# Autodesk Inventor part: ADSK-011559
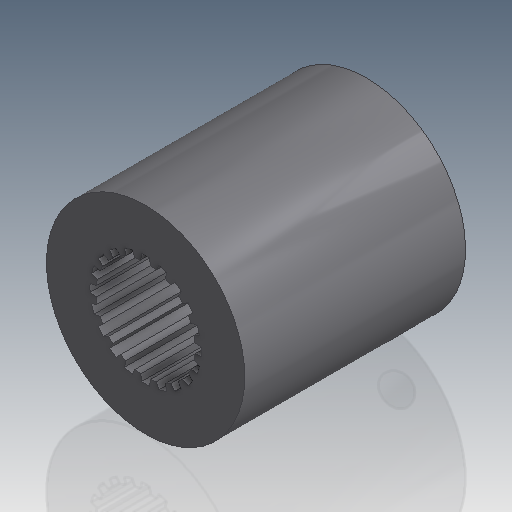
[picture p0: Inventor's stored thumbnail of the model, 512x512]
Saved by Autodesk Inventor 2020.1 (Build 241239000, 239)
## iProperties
Created: 2000-01
Part Number: ADSK-011559
Material: Pearson CRS
Document SubType Name: Modeling
Designer: tgregory
Density: 7.83 g/cm^3
Appearance: Metal-Steel(Polish)
Mass: 895.599 g
Surface Area: 250.505 cm^2
Volume: 114.381 cm^3
Control State: 0
Master: False
Checked Out: False
Shininess: 0.0
Length Units: 11269
Angle Units: 11279
Time Units: 11290
Mass Units: 11283
Length Display Precision: 3
Angle Display Precision: 2
Compacted: True
Dimensions: 57x63,5x57 mm
Mass: 0,896 kg
VLT_Material: Pearson CRS
Density: 0.0
Volumn: 0.0
Area: 0.0
PropertySet Name: Model Information
Author: tgregory
Revision Number: -
Title: ADSK-011559
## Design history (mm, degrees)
node "Solide1"
  node "Extrusion1" dims "d8" = 25, "d9" = 0
  node "Extrusion2" dims "d14" = 63.5, "d15" = 0
  node "Extrusion3" dims "d16" = 50.8, "d17" = 0
  node "Hole1" dims "d22" = 8.376, "d23" = 9.525, "d24" = 6.35, "d25" = 60 deg, "d26" = 27.3, "d27" = 118 deg, "d34" = 20
  node "Hole2" dims "d28" = 8.376, "d29" = 9.525, "d30" = 6.35, "d31" = 60 deg, "d32" = 27.3, "d33" = 118 deg, "d35" = 20
sketch "Sketch1"
  geometry: L1 (0, 16)-(0, 0) reference; L2 (1.4, 14.181)-(1.15, 15.959); L3 (-1.15, 15.959)-(-1.4, 14.181); A1 r 14.25 centre (0, 0) between (1.4, 14.181) and (-1.4, 14.181); A2 r 16 centre (0, 0) between (1.15, 15.959) and (-1.15, 15.959); 1 further point
  constraints: 6 end point, 4 point on circle, 3 coincident, 2 centre point, 1 vertical
  dimensions: "d0" = 28.5 diameter of A1; "d1" = 32 diameter of A2; "d4" = 1.15 distance from line of L2.end L1; "d5" = 1.4 distance from line of L2.start L1; "d6" = 1.15 distance from line of L3.start L1 (= d4); "d7" = 1.4 distance from line of L3.end L1 (= d5)
sketch "Sketch3"
  geometry: L1 (-28.5, 0)-(28.5, 0) reference; L2 (-28.5, 0)-(28.5, 0); L3 (28.5, 0)-(28.5, -25); L4 (28.5, -25)-(-28.5, -25); L5 (-28.5, -25)-(-28.5, 0); 2 further points
  constraints: 8 end point, 2 perpendicular, 1 horizontal, 1 parallel, 1 point on line, 1 other
workplane "Work Plane2"
workplane "Work Plane3"
workplane "Work Plane4"
workaxis "Work Axis2"
workaxis "Work Axis3"
workaxis "Work Axis1"
sketch "Sketch2"
  geometry: L1 (-5.714, -13.054)-(-6.025, -14.822) reference; L2 (-3.838, -15.533)-(-3.051, -13.92) reference; L3 (-1.4, -14.181)-(-1.15, -15.959) reference; L4 (1.15, -15.959)-(1.4, -14.181) reference; L5 (3.051, -13.92)-(3.838, -15.533) reference; L6 (6.025, -14.822)-(5.714, -13.054) reference; L7 (7.203, -12.296)-(8.45, -13.587) reference; L8 (10.311, -12.235)-(9.468, -10.65) reference; L9 (10.65, -9.468)-(12.235, -10.311) reference; L10 (13.587, -8.45)-(12.296, -7.203) reference; L11 (13.054, -5.714)-(14.822, -6.025) reference; L12 (15.533, -3.838)-(13.92, -3.051) reference; L13 (14.181, -1.4)-(15.959, -1.15) reference; L14 (15.959, 1.15)-(14.181, 1.4) reference; L15 (13.92, 3.051)-(15.533, 3.838) reference; L16 (14.822, 6.025)-(13.054, 5.714) reference; L17 (12.296, 7.203)-(13.587, 8.45) reference; L18 (12.235, 10.311)-(10.65, 9.468) reference; L19 (9.468, 10.65)-(10.311, 12.235) reference; L20 (8.45, 13.587)-(7.203, 12.296) reference; L21 (5.714, 13.054)-(6.025, 14.822) reference; L22 (3.838, 15.533)-(3.051, 13.92) reference; L23 (1.4, 14.181)-(1.15, 15.959) reference; L24 (-1.15, 15.959)-(-1.4, 14.181) reference; L25 (-3.051, 13.92)-(-3.838, 15.533) reference; L26 (-6.025, 14.822)-(-5.714, 13.054) reference; L27 (-7.203, 12.296)-(-8.45, 13.587) reference; L28 (-10.311, 12.235)-(-9.468, 10.65) reference; L29 (-10.65, 9.468)-(-12.235, 10.311) reference; L30 (-13.587, 8.45)-(-12.296, 7.203) reference; L31 (-13.054, 5.714)-(-14.822, 6.025) reference; L32 (-15.533, 3.838)-(-13.92, 3.051) reference; L33 (-14.181, 1.4)-(-15.959, 1.15) reference; L34 (-15.959, -1.15)-(-14.181, -1.4) reference; L35 (-13.92, -3.051)-(-15.533, -3.838) reference; L36 (-14.822, -6.025)-(-13.054, -5.714) reference; L37 (-12.296, -7.203)-(-13.587, -8.45) reference; L38 (-12.235, -10.311)-(-10.65, -9.468) reference; L39 (-9.468, -10.65)-(-10.311, -12.235) reference; L40 (-8.45, -13.587)-(-7.203, -12.296) reference; C1 r 28.5 at (0, 0); A1 r 16 centre (0, 0) between (-6.025, -14.822) and (-3.838, -15.533) reference; A2 r 14.25 centre (0, 0) between (-3.051, -13.92) and (-1.4, -14.181) reference; A3 r 16 centre (0, 0) between (-1.15, -15.959) and (1.15, -15.959) reference; A4 r 14.25 centre (0, 0) between (1.4, -14.181) and (3.051, -13.92) reference; A5 r 16 centre (0, 0) between (3.838, -15.533) and (6.025, -14.822) reference; A6 r 14.25 centre (0, 0) between (5.714, -13.054) and (7.203, -12.296) reference; A7 r 16 centre (0, 0) between (8.45, -13.587) and (10.311, -12.235) reference; A8 r 14.25 centre (0, 0) between (9.468, -10.65) and (10.65, -9.468) reference; A9 r 16 centre (0, 0) between (12.235, -10.311) and (13.587, -8.45) reference; A10 r 14.25 centre (0, 0) between (12.296, -7.203) and (13.054, -5.714) reference; A11 r 16 centre (0, 0) between (14.822, -6.025) and (15.533, -3.838) reference; A12 r 14.25 centre (0, 0) between (13.92, -3.051) and (14.181, -1.4) reference; A13 r 16 centre (0, 0) between (15.959, -1.15) and (15.959, 1.15) reference; A14 r 14.25 centre (0, 0) between (14.181, 1.4) and (13.92, 3.051) reference; A15 r 16 centre (0, 0) between (15.533, 3.838) and (14.822, 6.025) reference; A16 r 14.25 centre (0, 0) between (13.054, 5.714) and (12.296, 7.203) reference; A17 r 16 centre (0, 0) between (13.587, 8.45) and (12.235, 10.311) reference; A18 r 14.25 centre (0, 0) between (10.65, 9.468) and (9.468, 10.65) reference; A19 r 16 centre (0, 0) between (10.311, 12.235) and (8.45, 13.587) reference; A20 r 14.25 centre (0, 0) between (7.203, 12.296) and (5.714, 13.054) reference; A21 r 16 centre (0, 0) between (6.025, 14.822) and (3.838, 15.533) reference; A22 r 14.25 centre (0, 0) between (3.051, 13.92) and (1.4, 14.181) reference; A23 r 16 centre (0, 0) between (1.15, 15.959) and (-1.15, 15.959) reference; A24 r 14.25 centre (0, 0) between (-1.4, 14.181) and (-3.051, 13.92) reference; A25 r 16 centre (0, 0) between (-3.838, 15.533) and (-6.025, 14.822) reference; A26 r 14.25 centre (0, 0) between (-5.714, 13.054) and (-7.203, 12.296) reference; A27 r 16 centre (0, 0) between (-8.45, 13.587) and (-10.311, 12.235) reference; A28 r 14.25 centre (0, 0) between (-9.468, 10.65) and (-10.65, 9.468) reference; A29 r 16 centre (0, 0) between (-12.235, 10.311) and (-13.587, 8.45) reference; A30 r 14.25 centre (0, 0) between (-12.296, 7.203) and (-13.054, 5.714) reference; A31 r 16 centre (0, 0) between (-14.822, 6.025) and (-15.533, 3.838) reference; A32 r 14.25 centre (0, 0) between (-13.92, 3.051) and (-14.181, 1.4) reference; A33 r 16 centre (0, 0) between (-15.959, 1.15) and (-15.959, -1.15) reference; A34 r 14.25 centre (0, 0) between (-14.181, -1.4) and (-13.92, -3.051) reference; A35 r 16 centre (0, 0) between (-15.533, -3.838) and (-14.822, -6.025) reference; A36 r 14.25 centre (0, 0) between (-13.054, -5.714) and (-12.296, -7.203) reference; A37 r 16 centre (0, 0) between (-13.587, -8.45) and (-12.235, -10.311) reference; A38 r 14.25 centre (0, 0) between (-10.65, -9.468) and (-9.468, -10.65) reference; A39 r 16 centre (0, 0) between (-10.311, -12.235) and (-8.45, -13.587) reference; A40 r 14.25 centre (0, 0) between (-7.203, -12.296) and (-5.714, -13.054) reference
  constraints: 1 centre point, 1 coincident
  dimensions: "d13" = 57 diameter of C1
node "Corps solides"
node "Corps surfaciques"
node "Circular Pattern1" dims "d10" = 200, "d12" = 360 deg
sketch "Sketch4"
  geometry: 2 further points
  constraints: 1 coincident
sketch "Sketch5"
  geometry: 1 further point
other parameters: "d19" = 40 deg, "d20" = 40 deg, "d21" = -9.525
